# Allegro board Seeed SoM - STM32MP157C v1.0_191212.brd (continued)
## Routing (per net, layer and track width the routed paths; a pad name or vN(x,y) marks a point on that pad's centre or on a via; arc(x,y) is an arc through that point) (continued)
ETH_TX_EN: length 11.8
  TOP w0.089: U3.AB1 8.75,6.82 8.75,6.7 8.02,5.97 8.02,5.95 v1(7.84,5.78)
  LAYER_3 w0.127: v1(0.54,7.56) 0.54,5.76 0.77,5.53 6.43,5.53 6.66,5.76 7.43,5.76 7.45,5.78 v1(7.84,5.78)
  BOTTOM w0.127: J1.28 0.88,7.53 0.86,7.56 v1(0.54,7.56)
ETH_TXD0: length 11.6
  TOP w0.089: U3.AA2 9.13,7.21 8.67,7.21 8.49,7.03 8.49,6.74 7.84,6.09 v1(7.29,6.09)
  LAYER_3 w0.127: v1(0.89,5.93) 0.89,6.2 1.01,6.32 1.45,6.32 1.58,6.19 1.58,5.99 1.71,5.86 2.79,5.86 2.92,5.99 2.92,6.06 3.05,6.19 3.3,6.19 3.43,6.06 3.43,5.99 3.55,5.86 3.81,5.86 3.93,5.99 3.93,6.06 4.06,6.19 4.32,6.19 4.44,6.06 4.44,5.89 4.53,5.8 5.28,5.8 5.8,6.32 6.16,6.32 6.44,6.04 6.76,6.04 6.91,6.19 7.19,6.19 v1(7.29,6.09)
  BOTTOM w0.127: v1(0.89,5.93) J1.20
ETH_TXD1: length 11.8
  TOP w0.089: v1(7.85,6.54) 8.31,7.01 8.31,7.11 8.66,7.45 U3.AA1
  LAYER_3 w0.127: v1(2.01,6.44) 2.2,6.25 2.55,6.25 2.72,6.42 2.72,7 2.82,7.1 3.09,7.1 3.21,6.98 3.21,6.59 3.34,6.47 3.59,6.47 3.72,6.59 3.72,6.98 3.85,7.1 4.08,7.1 4.2,6.98 4.2,6.59 4.33,6.47 4.56,6.47 4.69,6.59 4.69,6.98 4.81,7.1 5.06,7.1 5.16,7 5.16,6.62 5.26,6.52 5.52,6.52 5.64,6.65 5.64,6.98 5.77,7.1 6.15,7.1 6.7,6.54 v1(7.85,6.54)
  BOTTOM w0.127: J1.22 1.9,6.33 v1(2.01,6.44)
ETH_TXD2: length 11.6
  TOP w0.089: v1(7.29,6.87) 7.89,6.87 8.14,7.12 8.14,7.23 8.61,7.7 9.13,7.7 U3.Y2
  LAYER_3 w0.127: v1(7.29,6.87) 6.76,6.87 6.23,7.41 5.06,7.41 4.93,7.53 4.93,7.76 4.8,7.89 4.55,7.89 4.42,7.76 4.42,7.53 4.3,7.41 4.04,7.41 3.91,7.53 3.91,7.76 3.79,7.89 3.53,7.89 3.41,7.76 3.41,7.53 3.28,7.41 1.73,7.41 1.58,7.26 1.58,6.9 1.38,6.7 v1(0.89,6.7)
  BOTTOM w0.127: J1.24 1.43,6.72 0.97,6.72 0.94,6.7 v1(0.89,6.7)
ETH_TXD3: length 11.8
  TOP w0.089: v1(7.83,7.25) 7.9,7.25 8.6,7.95 U3.Y1
  LAYER_3 w0.127: v1(0.87,7.17) 1.22,7.52 1.22,8.07 1.45,8.3 2.28,8.3 2.4,8.17 2.4,7.97 2.53,7.84 2.79,7.84 2.91,7.97 2.91,8.17 3.04,8.3 3.71,8.3 3.84,8.42 3.84,8.83 3.97,8.96 4.22,8.96 4.35,8.83 4.35,8.42 4.48,8.3 5.03,8.3 5.59,7.74 6.43,7.74 6.92,7.25 v1(7.83,7.25)
  BOTTOM w0.127: v1(0.87,7.17) 0.9,7.13 J1.26
FDCAN1_RX: length 21.6
  TOP w0.089: v1(7.17,27.32) 7.55,27.32 9.02,25.85 11.3,25.85 11.37,25.78 12.31,25.78 12.67,25.42 12.67,22.87 13,22.55 13,21.98 12.47,21.45 12.47,18.53 12.63,18.37 12.63,17.2 U3.B8
  LAYER_5 w0.089: v1(7.17,27.32) 7.52,27.68 7.52,28.62 7.14,29 7.14,30.96 v1(7.32,31.13)
  BOTTOM w0.089: J4.68 8.22,31.68 7.68,31.13 v1(7.32,31.13)
FDCAN1_TX: length 21.4
  TOP w0.089: U3.B9 12.88,18.37 12.65,18.61 12.65,19.12 12.65,19.12 12.65,19.24 v1(12.82,19.41)
  LAYER_5 w0.089: v1(12.82,19.41) 12.65,19.59 12.65,21.02 13.82,22.19 13.82,23.23 14.81,24.22 14.81,26.71 13.42,28.11 13.42,29.23 11.13,31.51 8.2,31.51 v1(7.82,31.89)
  BOTTOM w0.089: J4.70 v1(7.82,31.89)
FDCAN2_RX: length 43.7
  TOP w0.089: v1(12.48,8.35) 12.47,8.35 12.38,8.26 U3.Y8
  LAYER_3 w0.089: v1(9.07,31.11) 9.55,30.62 13.71,30.62 13.89,30.45 17.54,30.45 17.89,30.8 v1(18.14,30.8)
  LAYER_5 w0.089: v1(12.48,8.35) 13.57,7.26 18.33,7.26 19.11,8.03 19.11,8.97 19.38,9.25 19.38,16.88 19.26,17.01 19.26,22.29 20.93,23.97 20.93,27.04 18.14,29.84 v1(18.14,30.8)
  BOTTOM w0.089: J4.64 9.02,31.4 9.07,31.35 v1(9.07,31.11)
FDCAN2_TX: length 50.1
  TOP w0.089: U3.AA10 v2(13.39,7.45)
  GND02 w0.089: v1(13.57,5.25) 13.39,5.43 v2(13.39,7.45)
  LAYER_3 w0.089: v1(19.54,30.62) 19.54,30.87 18.69,31.72 13.66,31.72 13.51,31.56 8.97,31.56 v1(8.64,31.89)
  LAYER_5 w0.089: v1(13.57,5.25) 13.57,5.65 14.15,6.24 16.03,6.24 16.9,5.37 19.73,5.37 20.18,5.82 20.18,15.56 21.34,16.71 21.34,17.98 22.55,19.19 22.55,21.3 23.14,21.89 23.14,25.84 19.54,29.45 v1(19.54,30.62)
  BOTTOM w0.089: J4.66 8.62,32.16 8.64,32.14 v1(8.64,31.89)
GPIO_PD4: length 22.4
  TOP w0.089: v1(12.48,34.18) 12.22,33.93 10.55,33.93 10.16,33.54 10.16,30.72 v1(10.59,30.29) ; v1(11.38,19.62) 11.38,19.61 11.31,19.54 11.31,19.32 11.46,19.17 11.46,18.68 11.38,18.6 U3.B6
  LAYER_5 w0.089: v1(11.38,19.62) 11.57,19.81 11.57,21.75 10.75,22.57 10.75,23.7 10.51,23.94 10.51,24.34 10.84,24.67 10.84,25.77 11.07,25.99 11.07,27.31 10.77,27.6 10.32,27.6 10.04,27.88 10.04,28.36 10.59,28.91 v1(10.59,30.29)
  BOTTOM w0.089: v1(12.48,34.18) 12.22,34.43 J4.47
GPIO_PE12: length 18.1
  TOP w0.089: v1(0.48,15.93) 1.29,15.93 2.16,16.81 3.43,16.81 4.45,17.82 4.45,20.72 4.32,20.84 v1(4.07,20.84) ; v1(9.9,19.37) 9.9,19.1 10.13,18.87 10.13,17.21 U3.B4
  LAYER_3 w0.089: v1(9.9,19.37) 5.54,19.37 v1(4.07,20.84)
  BOTTOM w0.089: J1.70 v1(0.48,15.93)
GPIO_PF3: length 42
  TOP w0.089: v1(7.84,9.41) 7.87,9.41 7.88,9.42 7.94,9.42 7.97,9.45 U3.U1
  LAYER_3 w0.089: v1(11.03,35.93) 11.03,36.41 10.67,36.77 6.56,36.77 3.87,34.08 3.08,34.08 2.27,33.26 v1(1.1,33.26)
  LAYER_5 w0.089: v1(7.84,9.41) 7,9.41 3.85,12.56 3.85,12.99 2.77,14.06 2.77,15.05 3.56,15.84 3.56,17.13 4.23,17.81 4.23,20.22 1.1,23.36 v1(1.1,33.26)
  BOTTOM w0.089: J4.53 11.02,35.93 v1(11.03,35.93)
GPIO_PF8: length 51.3
  TOP w0.089: v1(14.2,5.22) 14.2,5.38 13.88,5.7 U3.AC11
  LAYER_3 w0.089: v1(15.79,36.72) 14.93,35.86 11.96,35.86 v1(11.41,36.41)
  LAYER_5 w0.089: v1(14.2,5.22) 14.2,5.77 14.48,6.06 15.96,6.06 16.83,5.19 19.81,5.19 20.46,5.85 20.46,15.57 21.52,16.63 21.52,17.49 23.22,19.19 23.22,21.72 23.37,21.87 23.37,25.87 19.84,29.4 19.84,30.49 19.85,30.49 19.85,33.79 18.83,34.81 16.92,34.81 16.16,35.58 16.16,36.35 v1(15.79,36.72)
  BOTTOM w0.089: J4.51 11.42,36.15 11.41,36.16 v1(11.41,36.41)
GPIO_PF12: length 33.9
  TOP w0.089: U3.Y9 12.88,8.21 12.83,8.27 12.83,8.57 v1(13.13,8.87)
  LAYER_5 w0.089: v1(12.02,36.41) 11.82,36.22 11.82,31.18 13.64,29.35 13.64,28.29 15.09,26.84 15.09,25.26 14.99,25.16 14.99,24.12 14,23.13 14,21.89 13.8,21.68 13.8,18.94 13.24,18.38 13.24,15.1 13.11,14.97 13.11,14.26 12.85,14 12.52,14 11.62,13.1 11.62,10.63 11.61,10.62 11.61,9.62 11.87,9.36 12.65,9.36 v1(13.13,8.87)
  BOTTOM w0.089: v1(12.02,36.41) 12.02,36.11 11.94,36.04 11.94,35.96 11.82,35.84 J4.49
GPIO_PG3: length 33.7
  TOP w0.089: U3.T4 v1(10.65,9.95)
  LAYER_5 w0.089: v1(10.65,9.95) 10.22,10.39 10.22,11.81 8.95,13.08 8.95,15.13 8.01,16.07 8.01,17.06 7.47,17.59 7.47,18.2 7.7,18.43 7.7,20.08 7.32,20.46 7.32,23.76 7.48,23.92 7.48,25.09 6.84,25.73 6.84,32.78 7.35,33.29 7.35,35.5 6.94,35.91 v1(6.94,36.26)
  BOTTOM w0.089: R5.1 3.33,36.21 3.97,36.85 5.54,36.85 6.13,36.26 v1(6.94,36.26)
GPIO_PG11: length 47.2
  TOP w0.089: v1(11.82,8.35) 11.71,8.25 11.71,8.12 U3.Y7
  LAYER_3 w0.089: v1(10.6,36.06) 10.6,35.81 10.79,35.62 15.25,35.62 v1(15.81,36.18)
  LAYER_5 w0.089: v1(15.81,36.18) 15.81,35.51 16.92,34.39 16.92,33.16 18.57,31.51 18.57,29.66 21.9,26.33 21.9,21.76 20.58,20.44 20.58,18.08 19.56,17.06 19.56,9.17 19.28,8.89 19.28,7.95 18.36,7.03 13.14,7.03 v1(11.82,8.35)
  BOTTOM w0.089: J4.55 10.62,35.79 10.6,35.81 v1(10.6,36.06)
GPIO_PI3: length 19.8
  TOP w0.089: U3.E1 8.03,15.45 6.99,16.5 6.99,17.09 5.85,18.23 5.85,21.15 v1(6.15,21.45)
  LAYER_3 w0.089: v1(15.3,20.59) 14.64,20.59 14.49,20.74 14.18,20.74 13.98,20.94 13.98,20.94 13.54,21.38 12.35,21.38 12.22,21.5 11.74,21.5 11.73,21.51 11.48,21.51 11.4,21.59 11.4,21.82 11.31,21.91 11.13,21.91 11.04,21.82 11.04,21.59 10.96,21.51 10.77,21.51 10.69,21.59 10.69,21.82 10.6,21.91 10.42,21.91 10.33,21.82 10.33,21.59 10.25,21.51 10.13,21.51 10.13,21.5 6.45,21.5 6.4,21.45 v1(6.15,21.45)
  BOTTOM w0.089: J2.39 15.43,20.97 15.3,20.84 v1(15.3,20.59)
GPIO_PZ4: length 35.4
  TOP w0.089: U3.G2 9.13,14.21 7.91,14.21 5.03,17.08 5.03,22.2 2.55,24.68 2.55,32.86 6.45,36.77 12.33,36.77 v1(12.5,36.59)
  BOTTOM w0.089: J4.45 12.62,36.22 12.5,36.34 v1(12.5,36.59)
HDMI_CEC: length 25
  TOP w0.089: v1(15.14,8.88) 15.32,8.71 15.32,8.68 15.47,8.52 15.47,8.29 15.38,8.19 U3.Y14
  LAYER_3 w0.127: v1(3.51,3.32) 4.07,3.32 4.78,4.03 6.2,4.03 6.61,3.62 6.61,2.51 7.83,1.29 10.29,1.29 10.81,0.77 15.52,0.77 15.88,1.12 15.88,1.84 15.38,2.35 15.38,7.25 14.8,7.83 14.8,8.53 v1(15.14,8.88)
  BOTTOM w0.127: J1.7 3.73,3.53 v1(3.51,3.32)
HDMI_INT: length 9.1
  TOP w0.089: v1(7.8,7.87) 8.39,8.45 U3.W1
  LAYER_5 w0.127: v1(3.54,3.93) 3.76,4.16 3.76,6.32 5.32,7.87 v1(7.8,7.87)
  BOTTOM w0.127: J1.9 v1(3.54,3.93)
HDMI_NRST: length 22.4
  TOP w0.089: U3.Y17 v2(16.88,7.95)
  GND02 w0.127: v1(17.23,6.26) 17.23,6.53 17.02,6.73 17.02,7.79 16.88,7.93 v2(16.88,7.95)
  LAYER_3 w0.127: v1(4.93,3.52) 4.93,2.96 7.35,0.55 15.68,0.55 16.67,1.54 16.67,3.82 16.18,4.3 16.18,5.22 v1(17.23,6.26)
  BOTTOM w0.127: J1.11 4.75,4.33 4.93,4.16 v1(4.93,3.52)
HES_OUT: length 6
  TOP w0.089: U3.P2 9.13,11.2 8.78,11.2 8.71,11.13 7.91,11.13 7.69,11.36 6.88,11.36 6.23,10.71 R89.2
  TOP w0.127: R90.2 4.82,10.11 4.84,10.12 R89.2
HSE_IN: length 13
  TOP w0.089: R4.2 5.16,2.91 5.36,3.11 5.36,3.95 6.07,4.65 6.07,5.48 5.71,5.83 5.71,6.13 5.9,6.32 6.02,6.43 6.16,6.43 6.41,6.68 6.41,7.59 5.23,8.77 5.23,9.96 5.76,10.49 6.32,10.49 6.98,11.16 7.55,11.16 7.78,10.93 8.68,10.93 8.7,10.95 U3.P1
I2C1_SCL: length 49.5
  TOP w0.089: v1(8.95,4) 9.15,4 10.38,5.23 U3.AC4
  LAYER_3 w0.089: v1(18.38,34.39) 18.13,34.39 18.09,34.43 15.9,34.43 v1(15.73,34.26)
  LAYER_5 w0.089: v1(8.95,4) 9.12,4 11.79,6.67 18.5,6.67 19.79,7.96 19.79,15.66 20.93,16.81 20.93,18.08 22.18,19.32 22.18,21.43 22.64,21.89 22.64,25.85 18.78,29.71 18.78,33.99 v1(18.38,34.39)
  BOTTOM w0.089: v1(15.73,34.26) 15.42,33.95 J4.32
I2C1_SDA: length 49.8
  GND02 w0.089: v2(10.38,7.95) 10.12,7.69 10.12,6.64 10.19,6.57 10.19,3.88 v1(9.9,3.6)
  LAYER_3 w0.089: v1(19.09,30.62) 18.33,31.39 v1(15.96,31.39)
  LAYER_5 w0.089: v1(9.9,3.6) 9.9,4.48 11.92,6.49 16.03,6.49 16.98,5.55 19.66,5.55 20.01,5.9 20.01,15.63 21.14,16.76 21.14,18.03 22.36,19.25 22.36,21.35 22.92,21.91 22.92,25.82 19.11,29.63 19.11,30.36 19.09,30.38 v1(19.09,30.62)
  BOTTOM w0.089: J4.34 15.02,31.92 15.56,31.39 v1(15.96,31.39)
I2C2_SCL: length 47.2
  TOP w0.089: U3.B3 9.63,17.21 9.63,17.74 9.29,18.08 9.29,18.72 9.28,18.74 9.28,19.4 8.39,20.29 8.39,22.72 8.82,23.16 8.82,23.49 8.13,24.17 7.5,24.17 6.74,24.93 6.74,28.41 6.96,28.64 8.08,28.64 8.21,28.51 8.74,28.51 9.61,27.65 v1(9.61,27.1) ; R151.2 27.01,25.72 26.95,25.77 v1(26.95,25.92) 26.95,26.18 27.41,26.64 28.19,26.64 28.87,27.32 U2.4
  LAYER_3 w0.089: v1(9.61,27.1) 9.61,26.76 9.92,26.44 10.79,26.44 11.43,27.09 12.4,27.09 13.16,26.33 13.7,26.33 14.2,25.82 14.68,25.82 15.03,26.17 16.73,26.17 16.83,26.07 19,26.07 19.02,26.05 19.83,26.05 20.19,26.41 20.19,26.53 20.43,26.76 22.82,26.76 24.09,25.49 26.27,25.49 26.7,25.92 v1(26.95,25.92)
  BOTTOM w0.089: v1(9.61,27.1) 9.61,26.51 10.24,25.87 13.29,25.87 13.83,25.33 J2.32
I2C2_SDA: length 48.1
  TOP w0.089: U2.3 28.47,27.32 28.05,26.89 26.78,26.89 v1(25.8,25.91) 26.01,25.7 R152.2 ; v1(8.34,28.82) 8.14,29.02 6.99,29.02 6.56,28.59 6.56,24.86 7.47,23.94 7.88,23.94 8.18,23.64 8.18,21.61 7.68,21.1 7.68,20.64 9.1,19.22 9.1,18.66 9.11,18.65 9.11,18.01 9.38,17.74 U3.A2
  LAYER_3 w0.089: v1(25.8,25.91) 25.05,26.66 25.05,27.27 24.21,28.11 20.66,28.11 19.61,27.07 19.21,27.07 18.96,26.81 18.04,26.81 17.07,27.78 9.38,27.78 v1(8.34,28.82)
  BOTTOM w0.089: J2.34 14.23,25.18 13.36,26.05 10.44,26.05 9.91,26.58 9.91,27.52 8.79,28.63 8.55,28.63 8.54,28.65 8.51,28.65 v1(8.34,28.82)
I2S2_CK: length 11.2
  TOP w0.089: 6.89,6 6.96,6.08 6.96,7.05 7.47,7.56 7.95,7.56 8.6,8.2 9.63,8.2 U3.Y3
  TOP w0.127: 6.89,6 6.89,2.68 6.08,1.87 v1(5.34,1.87)
  BOTTOM w0.127: J1.1 4.9,2.33 5.15,2.08 5.15,2.06 v1(5.34,1.87)
I2S2_SDO: length 10.7
  TOP w0.089: 6.67,6.15 6.79,6.26 6.79,7.38 7.65,8.25 7.9,8.25 8.36,8.7 9.13,8.7 U3.W2
  TOP w0.127: 6.67,6.15 6.67,2.92 6.21,2.47 v1(5.94,2.47)
  BOTTOM w0.127: v1(5.94,2.47) 5.27,3.13 J1.5
I2S2_WS: length 9.5
  TOP w0.089: U3.AC5 10.88,5.2 8.46,2.78 8.18,2.78 v1(8.01,2.61)
  BOTTOM w0.127: v1(8.01,2.61) 7.51,2.11 5.63,2.11 5.01,2.73 J1.3
JTDI: length 27.3
  TOP w0.089: U3.A20 18.38,18.91 19.18,19.71 19.18,20.44 19.36,20.62 19.36,20.97 20.2,21.81 20.83,21.81 21.54,22.52 21.54,24.53 21.92,24.91 21.92,26.89 19.84,28.97 19.84,30.49 19.85,30.49 19.85,31.63 v1(19.46,32.02)
  LAYER_3 w0.089: v1(10.6,32.09) 11.14,32.63 14.66,32.63 14.96,32.33 19.15,32.33 v1(19.46,32.02)
  BOTTOM w0.089: v1(10.6,32.09) 10.62,32.12 J4.56
JTDO_TRACESWO: length 30.8
  TOP w0.089: v1(10.06,34.56) 10.37,34.26 11.81,34.26 12.28,34.73 18.01,34.73 18.04,34.69 18.83,34.69 19.01,34.5 19.01,34.5 19.06,34.45 19.06,33.95 18.76,33.65 18.76,29.8 21.04,27.52 21.04,23.71 20.32,23 20.32,22.44 19,21.12 19,20.76 18.83,20.58 18.83,19.85 18.01,19.04 18.01,17.77 17.88,17.64 U3.A19
  BOTTOM w0.089: J4.58 10.22,34.15 10.06,34.31 v1(10.06,34.56)
JTRST: length 30.3
  TOP w0.076: 19.08,29.2 18.99,29.29
  TOP w0.089: 18.99,29.29 18.57,29.71 18.57,33.75 17.76,34.56 12.35,34.56 11.88,34.09 10.48,34.09 10.39,34 9.86,34 v1(9.68,34.18) ; 19.08,29.2 20.83,27.45 20.83,23.76 20.12,23.05 20.12,22.49 18.83,21.2 18.83,20.87 18.65,20.69 18.65,19.93 17.81,19.09 17.81,17.82 17.63,17.64 17.63,17.2 U3.B19
  BOTTOM w0.089: v1(9.68,34.18) 9.68,33.93 9.82,33.79 J4.60
LES_OUT: length 3.9
  TOP w0.089: 6.6,12.43 7.02,12.43 7.04,12.45 U3.L1
  TOP w0.127: 6.6,12.43 R79.2
LPO_32K: length 24.5
  TOP w0.089: v1(10.7,12.51) 10.65,12.45 U3.L4
  LAYER_3 w0.089: v1(8.64,25.24) 9.15,25.75 12.22,25.75 12.4,25.92 13.33,25.92 13.84,25.42 14.89,25.42 15.43,24.88 17.05,24.88 17.18,25.01 v1(17.43,25.01)
  LAYER_5 w0.089: v1(10.7,12.51) 9.81,13.41 9.81,17.75 9.28,18.28 9.28,19.37 8.56,20.08 8.56,22.55 9,22.98 9,24.5 8.64,24.86 v1(8.64,25.24)
  BOTTOM w0.089: J2.50 v1(17.43,25.01)
LSE_IN: length 4.8
  TOP w0.089: U3.L2 9.13,12.7 6.59,12.7
  TOP w0.127: 6.59,12.7 6.58,12.69 6.1,12.69 5.35,13.44 R2.1
LTDC_B0: length 15.9
  TOP w0.089: U3.K1 7.77,12.95 7.71,13.01 v1(7.46,13.01)
  BOTTOM w0.089: v1(7.46,13.01) 7.95,13.01 8.04,13.1 8.04,13.62 8.13,13.71 8.3,13.71 8.39,13.62 8.39,13.1 8.48,13.01 9.26,13.01 9.4,12.87 9.4,11.9 9.33,11.83 7.98,11.83 7.78,11.62 7.78,10.68 7.9,10.56 8.69,10.56 8.79,10.46 8.79,9.95 8.59,9.74 7.6,9.74 7.29,9.44 5.16,9.44 4.7,8.98 4.7,8.08 4.55,7.93 J1.29
LTDC_B1: length 16.2
  TOP w0.089: v1(11.03,12.92) 10.78,12.92 10.76,12.94 10.58,12.94 10.57,12.95 U3.K4
  LAYER_3 w0.089: v1(3.1,11.67) 2.93,11.85 2.93,12.1 2.7,12.34 2.7,12.49 2.82,12.61 2.98,12.61 3.26,12.34 3.48,12.34 3.75,12.61 4.1,12.61 4.19,12.52 4.19,12.3 4.28,12.21 4.46,12.21 4.55,12.3 4.55,12.52 4.64,12.61 5.13,12.61 5.23,12.7 7.59,12.7 7.8,12.92 v1(11.03,12.92)
  BOTTOM w0.089: J1.27 3.43,7.53 2.87,8.09 2.87,11.45 v1(3.1,11.67)
LTDC_B2: length 17.5
  TOP w0.089: v1(14.4,4.72) 14.4,4.96 14.53,5.1 14.53,5.32 14.15,5.71 14.15,6.68 U3.AB11
  LAYER_3 w0.089: v1(5.56,9.11) 5.78,9.34 7.46,9.34 7.71,9.09 8.55,9.09 8.87,8.78 8.87,7.38 10.39,5.86 12.37,5.86 13.71,4.53 14.21,4.53 v1(14.4,4.72)
  BOTTOM w0.089: v1(5.56,9.11) 5.09,9.11 4.88,8.9 4.88,7.43 4.58,7.13 J1.25
LTDC_B3: length 22.7
  TOP w0.089: v1(10.6,19.21) 10.6,18.96 10.63,18.92 10.63,17.21 U3.B5
  LAYER_3 w0.089: v1(2.86,16.27) 4.29,16.27 5.32,17.29 9.61,17.29 10.6,18.28 v1(10.6,19.21)
  BOTTOM w0.089: J1.23 3.42,6.73 2.7,7.46 2.7,10.79 2.4,11.09 2.4,15.05 2.86,15.51 v1(2.86,16.27)
LTDC_B4: length 20.4
  TOP w0.089: U3.E4 10.57,15.45 v1(10.67,15.35)
  LAYER_3 w0.089: v1(10.67,15.35) 10.36,15.66 5.18,15.66 4.92,15.92 2.62,15.92 v1(2.44,16.09)
  BOTTOM w0.089: J1.21 2.93,6.33 2.5,6.77 2.5,7.33 2.49,7.34 2.49,10.68 2.22,10.96 2.22,15.13 2.62,15.53 2.62,15.92 v1(2.44,16.09)
LTDC_B5: length 16.1
  TOP w0.089: v1(7.35,9.01) 7.88,9.01 8.08,9.21 9.13,9.21 U3.U2
  LAYER_6 w0.089: v1(6.07,9.01) 5.71,8.65 5.71,8.53 5.62,8.44 5.43,8.44 5.34,8.35 5.34,8.17 5.43,8.08 5.62,8.08 5.71,7.99 5.71,7.81 5.62,7.73 5.43,7.73 5.34,7.64 5.34,7.46 5.43,7.37 5.62,7.37 5.71,7.28 5.71,7.1 5.62,7.01 5.43,7.01 5.34,6.93 5.34,6.75 5.43,6.66 5.62,6.66 5.71,6.57 5.71,6.42 5.82,6.32 6.79,6.32 6.91,6.44 6.91,8.88 7.04,9.01 v1(7.35,9.01)
  BOTTOM w0.089: v1(6.07,9.01) 5.82,8.75 5.26,8.75 5.14,8.63 5.14,7 5.05,6.91 4.79,6.91 4.7,6.83 4.7,6.65 4.79,6.56 5.05,6.56 5.14,6.47 5.14,6.14 4.93,5.93 J1.19
LTDC_B6: length 18.6
  TOP w0.089: U3.AB10 13.11,6.68 13.11,6.32 13.2,6.22 13.2,5.59 13.06,5.44 13.06,5.05 13.7,4.41 13.7,2.07 13.77,1.99 v1(13.77,1.74)
  LAYER_3 w0.127: v1(7.4,2.61) 8.34,1.67 10.33,1.67 10.88,1.12 13.14,1.12 v1(13.77,1.74)
  BOTTOM w0.089: v1(7.4,2.61) 6.99,3.01 6.99,5.05 6.5,5.53 J1.17
LTDC_B7: length 22.6
  TOP w0.089: v1(10.93,13.35) 10.75,13.35 10.6,13.2 10.13,13.2 U3.K3
  LAYER_3 w0.089: v1(2.23,15.68) 2.48,15.68 2.49,15.66 3.2,15.66 4.68,14.19 10.09,14.19 v1(10.93,13.35)
  BOTTOM w0.089: J1.15 3.73,5.13 2.32,6.54 2.32,7.26 2.32,7.26 2.32,10.56 2.04,10.83 2.04,15.48 2.05,15.5 2.05,15.5 v1(2.23,15.68)
LTDC_CLK: length 23.9
  TOP w0.089: v1(15.71,3.65) 15.71,3.97 15.45,4.23 15.45,5.81 15.38,5.87 U3.AC14
  LAYER_6 w0.089: v1(15.71,3.65) 15.2,3.14 11.05,3.14 9.25,4.94 9.25,9.97 8.23,10.99 7.27,10.99 6.78,11.48 6.78,13.69 5.59,14.88 v1(4.98,14.88)
  BOTTOM w0.127: J1.63 4.84,14.73 v1(4.98,14.88)
LTDC_DE: length 21.9
  TOP w0.089: v1(14.43,8.35) 14.38,8.3 U3.Y12
  LAYER_3 w0.089: v1(14.43,8.35) 13.97,7.89 11.82,7.89 11.43,8.27 11.43,10.19 9.15,12.47 6.95,12.47 6.58,12.11 4.91,12.11 4.22,11.42 3.36,11.42 2.85,10.91 2.43,10.91 2.34,11 2.34,14.44 2.81,14.91 v1(3.24,14.91)
  BOTTOM w0.089: v1(3.24,14.91) 3.42,15.09 3.44,15.09 3.49,15.13 J1.65
LTDC_G0: length 18.9
  TOP w0.089: v1(11.22,20.13) 11.47,20.13 11.69,19.91 11.69,18.66 11.63,18.6 11.63,16.7 U3.C6
  LAYER_3 w0.089: v1(7.19,20.08) 7.43,20.08 7.58,19.93 10.04,19.93 10.09,19.98 10.82,19.98 10.97,20.13 v1(11.22,20.13)
  BOTTOM w0.089: J1.45 4.7,11.13 4.91,11.34 4.91,11.82 5.72,12.64 5.72,13.99 6.05,14.32 6.05,14.55 6.46,14.95 6.46,16.72 7.22,17.48 7.22,19.8 7.19,19.83 v1(7.19,20.08)
LTDC_G1: length 15.3
  TOP w0.089: U3.C10 13.63,16.21 13.63,15.47 13.86,15.24 v1(13.86,15.12)
  LAYER_3 w0.089: v1(6.46,14.52) 10.73,14.52 11.27,13.98 12.85,13.98 13.14,14.27 13.14,14.94 13.49,15.29 13.69,15.29 v1(13.86,15.12)
  BOTTOM w0.089: v1(6.46,14.52) 6.23,14.28 6.23,14.24 5.92,13.94 5.92,12.59 5.08,11.75 5.08,10.96 4.86,10.73 J1.43
LTDC_G2: length 15.4
  TOP w0.089: v1(7.55,16.98) 7.55,16.51 8.11,15.95 U3.D1
  BOTTOM w0.089: v1(7.55,16.98) 7.33,16.75 6.76,16.75 6.7,16.69 6.7,16.39 6.76,16.32 7.47,16.32 7.55,16.24 7.55,16.04 7.47,15.95 6.75,15.95 6.66,15.87 6.66,15.69 6.75,15.6 7.47,15.6 7.55,15.51 7.55,15.33 7.47,15.24 6.75,15.24 6.66,15.15 6.66,14.98 6.75,14.89 7.47,14.89 7.55,14.8 7.55,14.68 7.47,14.6 7.02,14.6 6.18,13.75 6.18,13.3 6.16,13.29 6.16,12.58 5.26,11.67 5.26,10.66 4.94,10.33 J1.41
LTDC_G3: length 18
  TOP w0.089: U3.C3 v2(9.89,16.45)
  GND02 w0.089: v1(9.97,20.38) 9.97,20.13 9.88,20.04 9.88,20.04 9.35,19.51 9.35,18.66 9.89,18.12 v2(9.89,16.45)
  BOTTOM w0.089: J1.39 4.89,9.93 5.44,10.48 5.44,11.6 6.34,12.5 6.34,13.09 6.35,13.1 6.35,13.68 7.07,14.39 7.65,14.39 7.8,14.54 7.8,16.78 8.13,17.1 8.13,18.52 8.29,18.68 8.29,18.7 v1(9.97,20.38)
LTDC_G4: length 18.4
  TOP w0.089: v1(8.56,18.2) 8.26,17.9 8.26,17.57 U3.B1
  BOTTOM w0.089: J1.37 4.75,9.53 5.62,10.4 5.62,11.49 6.53,12.41 6.53,13.61 7.14,14.21 7.8,14.21 8.01,14.42 8.01,16.73 8.22,16.94 8.7,16.94 8.79,16.85 8.79,16.56 8.88,16.48 9.05,16.48 9.14,16.56 9.14,16.85 9.23,16.94 9.49,16.94 9.58,16.85 9.58,16.49 9.67,16.4 9.85,16.4 9.94,16.49 9.94,16.85 10.03,16.94 10.28,16.94 10.37,17.03 10.37,17.25 10.28,17.34 8.54,17.34 8.31,17.57 8.31,17.95 v1(8.56,18.2)
LTDC_G5: length 16.2
  TOP w0.089: v1(8.36,16.63) 8.36,16.54 8.45,16.45 U3.C1
  BOTTOM w0.089: J1.35 4.6,9.13 5.8,10.33 5.8,11.42 6.71,12.34 6.71,13.49 7.22,14 9.26,14 9.37,14.1 9.37,14.56 9.28,14.65 8.45,14.65 8.36,14.74 8.36,14.91 8.45,15 9.28,15 9.37,15.09 9.37,15.27 9.28,15.36 8.45,15.36 8.36,15.45 8.36,15.62 8.45,15.71 9.28,15.71 9.37,15.8 9.37,16.11 9.28,16.2 8.51,16.2 8.36,16.35 v1(8.36,16.63)
LTDC_G6: length 20.9
  TOP w0.089: U3.E3 9.63,15.2 8.03,15.2 6.76,16.48 6.76,16.87 v1(5.98,17.65)
  BOTTOM w0.089: J1.33 3.75,8.73 3.25,9.24 3.25,10.88 3.61,11.24 3.61,12 2.8,12.82 2.8,14.95 3.56,15.71 3.56,17.01 3.79,17.24 4.35,17.24 4.43,17.33 4.43,17.83 4.52,17.92 4.7,17.92 4.79,17.83 4.79,16.95 4.88,16.86 5.06,16.86 5.15,16.95 5.15,17.83 5.23,17.92 5.41,17.92 5.5,17.83 5.5,17.33 5.59,17.24 5.85,17.24 5.98,17.37 v1(5.98,17.65)
LTDC_G7: length 18.8
  TOP w0.089: v1(6.19,18.33) 7.24,17.28 7.24,16.5 8.04,15.7 9.13,15.7 U3.E2
  BOTTOM w0.089: v1(6.19,18.33) 4.58,18.33 3.38,17.14 3.38,15.79 2.57,14.98 2.57,12.69 3.43,11.83 3.43,11.37 3.05,10.99 3.05,8.55 3.27,8.33 J1.31
LTDC_HSYNC: length 15.5
  TOP w0.089: v1(7.34,9.95) 7.59,9.95 7.64,9.9 8.64,9.9 8.7,9.95 U3.T1
  LAYER_6 w0.089: v1(4.81,15.3) 3.96,15.3 3.87,15.21 3.87,14.44 3.97,14.34 5.54,14.34 5.74,14.14 5.74,13.52 5.83,13.43 6.44,13.43 6.53,13.34 6.53,13.16 6.44,13.07 5.83,13.07 5.74,12.98 5.74,12.8 5.83,12.72 6.44,12.72 6.53,12.63 6.53,12.45 6.44,12.36 5.83,12.36 5.74,12.27 5.74,12.09 5.83,12 6.44,12 6.53,11.92 6.53,11.74 6.44,11.65 5.83,11.65 5.74,11.56 5.74,10.81 6.6,9.95 v1(7.34,9.95)
  BOTTOM w0.089: v1(4.81,15.3) 4.81,15.36 4.63,15.53 J1.67
LTDC_R0: length 17.9
  TOP w0.089: v1(9.06,4.47) 9.36,4.47 10.13,5.24 10.13,6.71 U3.AB4
  LAYER_6 w0.089: v1(3.56,14.6) 3.56,14.35 3.82,14.09 4.7,14.09 5.57,13.22 5.57,10.66 6.61,9.62 7.61,9.62 7.73,9.74 8.06,9.74 9.02,8.78 9.02,4.76 9.06,4.72 v1(9.06,4.47)
  BOTTOM w0.127: v1(3.56,14.6) 3.56,14.54 3.61,14.49 3.61,14.46 3.73,14.33 J1.61
LTDC_R1: length 19.8
  GND02 w0.089: v1(9.33,3.17) 9.33,3.56 9.96,4.19 9.96,5.78 9.86,5.88 v2(9.86,7.46)
  LAYER_6 w0.089: v1(9.33,3.17) 8.59,3.9 8.59,5.35 8.38,5.56 8.38,8.78 8.08,9.08 7.72,9.08 7.44,9.36 6.56,9.36 5.36,10.56 5.36,13.02 4.55,13.83 v1(3.46,13.83)
  BOTTOM w0.127: J1.59 3.56,13.93 v1(3.46,13.83)
LTDC_R2: length 15.5
  TOP w0.089: v1(11.05,15.61) 11.05,15.78 U3.D5
  LAYER_3 w0.089: v1(4.85,16.24) 5.25,15.84 5.74,15.84 5.83,15.93 5.83,16.16 5.92,16.25 6.1,16.25 6.19,16.16 6.19,15.93 6.28,15.84 6.46,15.84 6.54,15.93 6.54,16.16 6.63,16.25 6.81,16.25 6.9,16.16 6.9,15.93 6.99,15.84 7.17,15.84 7.26,15.93 7.26,16.16 7.34,16.25 7.52,16.25 7.61,16.16 7.61,15.93 7.7,15.84 7.92,15.84 8.01,15.93 8.01,16.18 8.1,16.27 8.28,16.27 8.37,16.18 8.37,15.93 8.46,15.84 8.63,15.84 8.72,15.93 8.72,16.18 8.81,16.27 8.99,16.27 9.08,16.18 9.08,15.93 9.17,15.84 9.34,15.84 9.43,15.93 9.43,16.18 9.52,16.27 9.7,16.27 9.79,16.18 9.79,15.93 9.88,15.84 10.06,15.84 10.14,15.93 10.14,16.18 10.23,16.27 10.41,16.27 10.5,16.18 10.5,15.93 10.59,15.84 10.83,15.84 v1(11.05,15.61)
  BOTTOM w0.089: v1(4.85,16.24) 5.34,16.24 5.59,15.99 5.59,15.17 5.29,14.87 5.29,14.7 4.77,14.18 4.77,13.74 4.56,13.53 J1.57
LTDC_R3: length 16.3
  TOP w0.089: v1(10.6,19.65) 10.72,19.65 11.26,19.11 11.26,18.73 11.13,18.6 11.13,16.7 U3.C5
  LAYER_3 w0.089: v1(6.23,19.85) 6.55,19.85 6.72,19.68 10.13,19.68 10.17,19.65 v1(10.6,19.65)
  BOTTOM w0.089: v1(6.23,19.85) 6.29,19.85 6.38,19.76 6.38,18.58 6.55,18.41 6.55,17.57 5.88,16.9 5.88,15.19 5.49,14.8 5.49,14.62 4.98,14.11 4.98,13.56 4.55,13.13 J1.55
LTDC_R4: length 16.6
  TOP w0.089: U3.V3 v2(9.88,8.95)
  GND02 w0.089: v1(5.69,9.77) 5.87,9.59 7.58,9.59 7.71,9.72 8.49,9.72 9.25,8.95 v2(9.88,8.95)
  LAYER_6 w0.089: v1(5.69,9.77) 5,10.46 5,11.96 4.91,12.05 4.74,12.05 4.62,11.93 4.62,8.87 4.53,8.79 4.35,8.79 4.27,8.87 4.27,12.29 4.38,12.4 4.91,12.4 5,12.49 v1(5,12.92)
  BOTTOM w0.089: v1(5,12.92) 4.75,12.92 4.57,12.73 J1.53
LTDC_R5: length 18.7
  TOP w0.089: v1(7.96,3.6) 9,3.6 10.63,5.23 10.63,6.37 10.63,6.38 10.63,6.71 U3.AB5
  LAYER_6 w0.089: v1(3.54,12.83) 4.04,12.33 4.04,7.46 5.84,5.66 7.42,5.66 7.66,5.43 8.08,5.43 8.36,5.15 8.36,4 v1(7.96,3.6)
  BOTTOM w0.089: v1(3.54,12.83) 3.54,12.55 3.75,12.33 J1.51
LTDC_R6: length 15.8
  TOP w0.089: U3.B2 9.13,17.21 9.13,17.71 8.89,17.95 8.89,18.35 8.67,18.58 8.44,18.58 8.35,18.67 8.35,19.51 8.26,19.6 8.09,19.6 8,19.51 8,18.67 7.91,18.58 7.73,18.58 7.64,18.67 7.64,19.51 7.55,19.6 7.37,19.6 7.28,19.51 7.28,18.67 7.2,18.58 6.96,18.58 v1(6.73,18.81)
  BOTTOM w0.089: v1(6.73,18.81) 6.73,17.49 6.06,16.83 6.06,15.12 5.69,14.75 5.69,14.52 5.34,14.17 5.34,12.77 4.51,11.93 J1.49
LTDC_R7: length 17.2
  TOP w0.089: U3.D3 v2(9.88,15.96)
  GND02 w0.089: v2(9.88,15.96) 9.63,16.21 9.63,18.1 8.87,18.86 8.87,19.96 8.89,19.99 v1(8.89,20.24)
  BOTTOM w0.089: J1.47 4.56,11.53 4.68,11.65 4.68,11.85 5.54,12.72 5.54,14.09 5.87,14.42 5.87,14.68 6.25,15.06 6.25,16.73 6.28,16.75 6.28,16.79 7.04,17.55 7.04,18.94 6.63,19.35 6.63,19.96 7.06,20.39 8.5,20.39 8.65,20.24 v1(8.89,20.24)
LTDC_VSYNC: length 16.1
  TOP w0.089: U3.H4 10.51,14.08 10.51,14.11 11.17,14.77 11.21,14.77 11.26,14.82 v1(11.56,14.82)
  LAYER_3 w0.089: v1(5.28,15.3) 5.53,15.3 5.6,15.23 5.6,14.56 5.69,14.47 5.87,14.47 5.96,14.56 5.96,15.24 6.07,15.35 6.25,15.35 6.34,15.26 6.34,14.94 6.43,14.85 6.61,14.85 6.7,14.94 6.7,15.26 6.78,15.35 6.96,15.35 7.05,15.26 7.05,14.86 7.15,14.77 7.33,14.77 7.42,14.86 7.42,15.29 7.51,15.38 7.69,15.38 7.77,15.29 7.77,14.86 7.86,14.77 8.04,14.77 8.13,14.86 8.13,15.29 8.22,15.38 8.4,15.38 8.49,15.29 8.49,14.86 8.57,14.77 8.75,14.77 8.84,14.86 8.84,15.29 8.93,15.38 9.11,15.38 9.2,15.29 9.2,14.86 9.29,14.77 9.46,14.77 9.55,14.86 9.55,15.29 9.64,15.38 9.82,15.38 9.91,15.29 9.91,14.86 10,14.77 11.21,14.77 11.26,14.82 v1(11.56,14.82)
  BOTTOM w0.089: J1.69 4.65,15.93 v1(5.28,15.3)
MMC2_CLK: length 4.1
  TOP w0.089: v1(12.96,18.74) 13.13,18.56 13.13,17.97 13.13,17.97 13.13,16.7 U3.C9
  BOTTOM w0.089: v1(12.96,18.74) 12.02,17.79 R134.1
MMC2_CMD: length 27.3
  TOP w0.089: U3.A10 13.38,18.55 13.32,18.61 13.32,19.12 13.31,19.12 v1(13.31,19.37)
  BOTTOM w0.089: v1(13.31,19.37) 13.31,19.12 13.32,19.12 13.32,17.77 13.64,17.44 15.3,17.44 15.85,18 16.67,18 17.55,18.88 17.56,18.88 17.95,19.27 18.22,19.27 18.31,19.36 18.31,20.6 18.4,20.69 19.08,20.69 19.17,20.6 19.17,20.42 19.08,20.34 18.76,20.34 18.67,20.25 18.67,20.07 18.76,19.98 19.08,19.98 19.17,19.89 19.17,19.71 19.08,19.62 18.76,19.62 18.67,19.54 18.67,19.36 18.76,19.27 19.28,19.27 20.76,20.74 21.22,20.74 21.57,21.1 22.08,21.1 22.69,21.71 22.69,21.94 22.6,22.03 22.32,22.03 22.23,22.12 22.23,22.3 22.32,22.39 22.6,22.39 22.69,22.48 22.69,22.66 22.6,22.74 22.32,22.74 22.23,22.83 22.23,23.01 22.32,23.1 22.6,23.1 22.69,23.19 22.69,24.75 22.6,24.84 22.29,24.84 22.2,24.93 22.2,25.1 22.29,25.19 22.6,25.19 22.69,25.28 22.69,25.46 22.6,25.55 22.29,25.55 22.2,25.64 22.2,25.81 22.29,25.9 22.6,25.9 22.69,25.99 22.69,26.31 22.51,26.49 R133.1
MMC2_DAT0: length 31.4
  TOP w0.089: U3.C13 v2(14.91,16.45)
  GND02 w0.089: v2(14.91,16.45) 14.91,17.18 14.58,17.51 14.58,18.76 14.87,19.05 14.87,20.43 14.6,20.7 14.6,20.75 v1(14.29,21.07)
  LAYER_3 w0.089: v1(3.74,25.73) 3.74,25.42 3.97,25.19 4.73,25.19 4.81,25.26 4.81,25.77 4.88,25.85 6.46,25.85 6.56,25.75 6.56,25.39 6.48,25.31 5.62,25.31 5.52,25.21 5.52,24.41 5.43,24.32 4.64,24.32 4.55,24.23 4.55,23.56 4.68,23.43 5.69,23.43 5.77,23.36 5.77,23.16 5.69,23.08 4.64,23.08 4.55,22.99 4.55,22.77 4.65,22.67 5.59,22.67 5.74,22.52 5.74,22.34 5.62,22.22 5.16,22.22 5.06,22.11 5.06,21.91 5.16,21.81 6.24,21.81 6.31,21.73 9.86,21.73 10.27,22.14 10.51,22.14 10.6,22.23 10.6,23.38 10.7,23.49 11.08,23.49 11.18,23.38 11.18,22.34 11.74,21.78 13.42,21.78 14,21.2 14.15,21.2 14.29,21.07 v1(14.29,21.07)
  BOTTOM w0.089: R125.1 v1(3.74,25.73)
MMC2_DAT1: length 34
  TOP w0.089: U3.B12 14.38,18.84 14.74,19.2 14.74,21.07 13.82,21.99 13.82,23.18 14.1,23.46 14.1,25.6 13.42,26.28 11.57,26.28 11.47,26.38 9.55,26.38 9.07,26.86 9.07,27.63 8.84,27.87 v1(8.35,27.87)
  LAYER_3 w0.089: v1(3.78,29.08) 2.69,29.08 2.6,28.99 2.6,28.04 2.51,27.95 2.34,27.95 2.25,28.04 2.25,28.99 2.16,29.08 2.04,29.08 1.95,28.99 1.95,28.04 1.87,27.95 1.69,27.95 1.6,28.04 1.6,28.99 1.51,29.08 1.27,29.08 1.12,29.23 1.12,29.91 1.27,30.06 1.71,30.06 1.79,29.97 1.79,29.82 1.88,29.73 2.06,29.73 2.15,29.82 2.15,29.97 2.24,30.06 2.42,30.06 2.51,29.97 2.51,29.82 2.59,29.73 2.77,29.73 2.86,29.82 2.86,29.97 2.95,30.06 3.13,30.06 3.22,29.97 3.22,29.82 3.31,29.73 3.48,29.73 3.57,29.82 3.57,29.97 3.66,30.06 3.92,30.06 4.9,29.08 7.13,29.08 v1(8.35,27.87)
  BOTTOM w0.089: R126.1 v1(3.78,29.08)
MMC2_DAT2: length 31.8
  TOP w0.089: v1(8.77,27.5) 8.77,26.89 9.45,26.2 11.42,26.2 11.5,26.11 13.35,26.11 13.92,25.55 13.92,23.58 13.64,23.31 13.64,21.76 13.92,21.48 13.92,17.68 13.88,17.64 U3.A11
  LAYER_3 w0.089: v1(8.77,27.5) 8.77,27.88 7.37,29.28 7.36,29.28 7.27,29.37 7.27,29.59 7.18,29.68 7.01,29.68 6.92,29.59 6.92,29.37 6.83,29.28 6.65,29.28 6.56,29.37 6.56,30.15 6.47,30.24 6.3,30.24 6.21,30.15 6.21,29.37 6.12,29.28 5.59,29.28 5.47,29.4 5.47,30.24 5.29,30.41 5.04,30.41 4.95,30.5 4.95,31.09 4.86,31.18 4.68,31.18 4.6,31.09 4.6,30.15 4.51,30.06 4.33,30.06 4.24,30.15 4.24,31.09 4.15,31.18 2.67,31.18 2.52,31.03 2.52,30.52 2.63,30.41 v1(3.33,30.41)
  BOTTOM w0.089: R127.1 3.72,32.17 3.33,31.79 v1(3.33,30.41)
MMC2_DAT3: length 28.3
  TOP w0.089: U3.B13 14.61,17.23 14.61,18.76 14.92,19.07 14.92,21.24 14.02,22.14 14.02,23.1 14.28,23.36 14.28,25.65 13.49,26.44 11.64,26.44 11.53,26.56 9.63,26.56 9.25,26.94 9.25,27.69 8.68,28.26 v1(7.15,28.26)
  LAYER_3 w0.089: v1(7.15,28.26) 6.9,28.26 6.82,28.18 4.11,28.18 3.33,27.4 3.33,25.49 4.35,24.48 v1(4.35,22.19)
  BOTTOM w0.089: R128.1 4.36,22.2 v1(4.35,22.19)
MMC2_DAT4: length 29.5
  TOP w0.089: U3.A13 14.79,17.55 14.79,18.49 v1(15.37,19.07)
  LAYER_3 w0.089: v1(3.76,24.12) 3.76,23.76 3.7,23.69 3.5,23.69 3.41,23.6 3.41,23.43 3.5,23.34 3.7,23.34 3.79,23.25 3.79,23.07 3.7,22.98 3.5,22.98 3.41,22.89 3.41,22.71 3.5,22.63 3.7,22.63 3.79,22.54 3.79,22.36 3.7,22.27 3.5,22.27 3.41,22.18 3.41,22 3.5,21.91 3.7,21.91 3.79,21.83 3.79,21.5 4.07,21.23 4.47,21.23 5.29,20.41 5.54,20.41 5.63,20.5 5.63,20.65 5.72,20.74 5.89,20.74 5.98,20.65 5.98,20.5 6.07,20.41 6.25,20.41 6.34,20.5 6.34,20.65 6.43,20.74 6.61,20.74 6.69,20.65 6.69,20.5 6.78,20.41 6.96,20.41 7.05,20.5 7.05,20.65 7.14,20.74 7.32,20.74 7.41,20.65 7.41,20.5 7.5,20.41 8.49,20.41 8.77,20.69 11.54,20.69 11.82,20.41 11.82,19.31 11.73,19.22 11.45,19.22 11.36,19.13 11.36,18.95 11.45,18.86 11.73,18.86 11.82,18.77 11.82,18.6 11.73,18.51 11.45,18.51 11.36,18.42 11.36,18.24 11.45,18.15 11.73,18.15 11.82,18.06 11.82,17.8 12.2,17.42 12.51,17.42 12.6,17.5 12.6,17.96 12.68,18.05 12.86,18.05 12.95,17.96 12.95,17.5 13.04,17.42 13.22,17.42 13.31,17.5 13.31,17.96 13.4,18.05 13.57,18.05 13.66,17.96 13.66,17.5 13.75,17.42 13.93,17.42 14.02,17.5 14.02,17.96 14.11,18.05 14.28,18.05 14.37,17.96 14.37,17.5 14.46,17.42 15.3,17.42 15.54,17.66 15.54,18.89 v1(15.37,19.07)
  BOTTOM w0.089: v1(3.76,24.12) 4.02,24.12 4.03,24.14 R129.1
MMC2_DAT5: length 32
  TOP w0.089: U3.A8 12.38,18.37 12.27,18.48 12.27,22.56 12.5,22.79 12.5,25.3 12.17,25.62 10.5,25.62 10.47,25.65 8.36,25.65 8.23,25.52 8.23,24.58 8.16,24.5 7.97,24.5 7.88,24.59 7.88,24.86 7.79,24.95 7.57,24.95 7.48,25.04 7.48,25.21 7.57,25.3 7.79,25.3 7.88,25.39 7.88,25.57 7.79,25.66 7.57,25.66 7.48,25.75 7.48,25.92 7.57,26.01 7.79,26.01 7.88,26.1 7.88,26.66 7.68,26.86 v1(7.15,26.86)
  LAYER_3 w0.089: v1(3.75,27.36) 4,27.36 4.14,27.22 4.14,25.51 4.23,25.42 4.45,25.42 4.54,25.51 4.54,26.31 4.61,26.39 4.61,27.83 4.7,27.92 4.88,27.92 4.97,27.83 4.97,26.62 5.06,26.53 5.24,26.53 5.33,26.62 5.33,27.83 5.41,27.92 5.59,27.92 5.68,27.83 5.68,26.95 5.77,26.86 5.93,26.86 6.02,26.95 6.02,27.84 6.11,27.93 6.29,27.93 6.38,27.84 6.38,26.56 6.47,26.47 6.75,26.47 v1(7.15,26.86)
  BOTTOM w0.089: v1(3.75,27.36) 4,27.36 4.01,27.36 R130.1
MMC2_DAT6: length 31.9
  TOP w0.089: U3.C11 v2(13.85,16.45) ; v1(7.15,27.8) 7.4,27.8 9.17,26.03 11.36,26.03 11.44,25.95 13.27,25.95 13.74,25.47 13.74,24.52 13.65,24.43 13,24.43 12.91,24.34 12.91,24.17 13,24.08 13.65,24.08 13.74,23.99 13.74,23.66 13.47,23.38 13.47,21.68 13.74,21.41 13.74,20.86 13.53,20.65 13.46,20.65 v1(13.29,20.48)
  GND02 w0.089: v2(13.85,16.45) 13.18,16.45 12.22,17.42 12.22,20.39 12.31,20.48 v1(13.29,20.48)
  LAYER_3 w0.089: v1(3.28,28.69) 3.03,28.69 3.01,28.67 3,28.67 2.85,28.51 2.85,27.75 2.95,27.65 3.28,27.65 4.53,28.9 5.6,28.9 5.69,28.81 5.69,28.55 5.78,28.46 5.95,28.46 6.04,28.55 6.04,28.81 6.13,28.9 6.31,28.9 6.4,28.81 6.4,28.55 6.49,28.46 6.67,28.46 6.75,28.55 6.75,28.81 6.84,28.9 7.01,28.9 7.46,28.45 7.46,27.87 7.4,27.8 v1(7.15,27.8)
  BOTTOM w0.089: v1(3.28,28.69) 3.28,29.63 4.29,30.64 R131.1
MMC2_DAT7: length 30.8
  TOP w0.089: v1(14.33,19.28) 14.16,19.1 14.16,17.23 U3.B11
  LAYER_3 w0.089: v1(3,25.34) 3.18,25.16 3.41,25.16 4.1,24.47 4.1,23.99 3.99,23.88 3.99,21.63 4.2,21.43 4.98,21.43 5.41,21 6.91,21 7.24,21.33 10.2,21.33 10.21,21.33 11.66,21.33 11.99,21 11.99,20.5 12.08,20.41 12.18,20.41 12.27,20.32 12.27,20.15 12.18,20.06 12.08,20.06 11.99,19.97 11.99,19.79 12.08,19.7 12.18,19.7 12.27,19.61 12.27,19.44 12.18,19.35 12.08,19.35 11.99,19.26 11.99,18.81 12.45,18.35 14.18,18.35 14.33,18.51 v1(14.33,19.28)
  BOTTOM w0.089: R132.1 4.27,33.82 4.11,33.67 4.11,33.49 2.93,32.31 2.93,25.66 3,25.59 v1(3,25.34)
MOC1: length 13.8
  TOP w0.089: U3.N2 9.06,11.78 7.93,11.78 7.7,11.55 7.46,11.55 7.34,11.67 v1(7.19,11.67)
  LAYER_3 w0.089: v1(7.19,11.67) 4.85,11.67 4.4,11.22 3.41,11.22 2.93,10.73 2.25,10.73 2.11,10.87 2.11,14.24 v1(0.84,15.51)
  BOTTOM w0.089: J1.68 1.42,15.51 v1(0.84,15.51)
MOC2: length 43
  TOP w0.089: 8.6,10.29 9.05,10.29 U3.T2
  TOP w0.127: v1(8.39,10.22) 8.53,10.22 8.6,10.29
  LAYER_3 w0.089: v1(1.85,33.69) 2.1,33.69 2.13,33.72 2.14,33.72 2.8,34.38 3.87,34.38 6.48,37 12.65,37 13.01,36.64 v1(13.01,36.39)
  LAYER_5 w0.089: v1(1.85,33.69) 2.2,33.35 2.2,31.59 1.68,31.08 1.68,24.17 4.63,21.23 4.63,16.78 4.27,16.42 4.27,12.71 6.06,10.92 6.44,10.92 6.48,10.96 7.64,10.96 v1(8.39,10.22)
  BOTTOM w0.089: J4.43 13.02,36 13.01,36.01 v1(13.01,36.39)
NRST: length 48.9
  TOP w0.089: v1(11.16,12.45) 10.98,12.28 10.96,12.28 10.89,12.2 10.13,12.2 U3.M3 ; v1(24.41,27.42) 24.24,27.25 24.24,24.87 24.42,24.68 R153.1
  LAYER_3 w0.089: v1(8.34,27.37) 8.53,27.19 8.9,27.19 9.31,27.6 13.05,27.6 v1(13.99,26.66) 14.83,27.5 16.99,27.5 17.88,26.61 19,26.61 19.28,26.89 19.82,26.89 20.6,27.68 24.16,27.68 v1(24.41,27.42)
  LAYER_5 w0.089: v1(8.34,27.37) 8.34,27.13 8.31,27.1 8.31,24.88 8.82,24.37 8.82,23.05 8.39,22.62 8.39,19.9 9.07,19.22 9.07,18.1 9.55,17.62 9.55,13.22 10.58,12.2 10.91,12.2 v1(11.16,12.45) ; v1(10.57,31.13) 10.89,30.81 10.89,29.76 v1(13.99,26.66)
  BOTTOM w0.089: v1(10.57,31.13) 10.82,31.13 10.83,31.12 11.05,31.12 11.82,31.9 J4.50 ; v1(13.99,26.66) 14,26.67 14,26.7 14.37,27.07 R135.1
OTG_FS_DM: length 65.4
  TOP w0.089: U3.AA18 v2(17.38,7.46)
  GND02 w0.089: v2(17.38,7.46) 17.38,6.69 17.87,6.21 17.87,5.47 18.88,4.46 18.88,3.32 18.88,3.32 18.88,3.09 19.41,2.56 19.77,2.56 v1(19.99,2.33)
  LAYER_6 w0.135: v1(19.99,2.33) 20.11,2.45 20.68,2.45 21.01,2.77 21.01,6.02 19.65,7.38 19.65,17.26 22.84,20.46 25.12,20.46 26.6,21.94 26.6,29.02 25.35,30.28 14.58,30.28 13.64,29.34 11.87,29.34 11.46,29.74 8.14,29.74 8,29.88 8,30.34 v1(8.18,30.52)
  BOTTOM w0.114: J2.4 8.23,24.86 8.17,24.92 8.17,26.46 7.98,26.65 7.98,30.32 v1(8.18,30.52)
OTG_FS_DP: length 65.3
  TOP w0.089: U3.AB19 17.88,6.96 v2(17.86,6.96)
  GND02 w0.089: v2(17.86,6.96) 17.79,6.96 17.68,6.85 17.68,6.67 18.14,6.21 18.14,5.48 18.41,5.21 18.53,5.21 18.75,5.43 18.85,5.43 19,5.27 19,5.15 18.81,4.96 18.81,4.8 19.13,4.49 19.13,3.14 19.51,2.77 19.88,2.77 v1(20.02,2.91)
  LAYER_6 w0.135: v1(7.5,30.52) 7.68,30.34 7.68,29.75 8.01,29.43 8.7,29.43 8.83,29.29 8.83,29.16 8.97,29.02 9.24,29.02 9.37,29.16 9.37,29.29 9.51,29.43 11.33,29.43 11.74,29.02 13.77,29.02 14.71,29.96 25.22,29.96 26.29,28.89 26.29,22.07 24.99,20.77 22.71,20.77 19.33,17.39 19.33,7.26 20.7,5.89 20.7,2.9 20.55,2.76 20.17,2.76 v1(20.02,2.91)
  BOTTOM w0.114: v1(7.5,30.52) 7.7,30.32 7.7,26.53 7.89,26.34 7.89,24.92 7.83,24.86 J2.2
OTG_VBUS: length 46.3
  TOP w0.089: v1(18.57,3.83) 18.9,4.16 18.9,4.82 17.88,5.84 U3.AC19
  LAYER_5 w0.076: 22.92,16.3 22.92,11.86 22.6,11.54
  LAYER_5 w0.089: v1(18.57,3.83) 19.2,3.19 19.71,3.19 21.24,4.72 21.24,9.19 21.51,9.46 21.51,10.45 22.6,11.54 ; 22.92,16.3 22.92,17.22 23.93,18.23 23.93,21.4 24.36,21.83 24.36,25.77 v1(23.8,26.33)
  LAYER_6 w0.089: v1(23.8,26.33) 23.19,25.72 19.27,25.72 17.87,24.32 9.66,24.32 v1(9.05,24.93)
  BOTTOM w0.203: J2.8 9.03,24.92 v1(9.05,24.93)
PA0_WKUP: length 72.3
  TOP w0.089: U3.AB3 9.63,6.7 9.63,5.93 8.36,4.66 v1(7.32,4.66) ; v1(25.69,28.18) 25.86,28.35 25.92,28.35 26.41,28.84 U2.43
  LAYER_3 w0.089: v1(0.72,32.71) 2.19,32.71 3.23,33.75 5.37,33.75 5.75,34.13 6.01,34.13 6.39,33.75 12.63,33.75 v1(12.96,34.08) 14.25,35.37 22.71,35.37 24.67,33.42 24.67,30.75 25.69,29.73 v1(25.69,28.18)
  LAYER_5 w0.089: v1(0.72,32.71) 0.92,32.5 0.92,23.29 4.06,20.15 4.06,17.91 3.38,17.24 3.38,15.91 2.54,15.08 2.54,13.33 5.79,10.08 5.82,10.08 6.01,9.9 6.01,9.86 7.17,8.7 7.39,8.7 7.72,8.37 7.76,8.37 8.36,7.76 8.36,4.94 8.08,4.66 v1(7.32,4.66)
  BOTTOM w0.089: J4.44 13.02,33.77 12.96,33.83 v1(12.96,34.08)
PMIC_WAKEUP: length 57
  TOP w0.089: v1(7.09,13.33) 7.68,13.33 7.78,13.22 9.11,13.22 U3.K2 ; v1(25.76,26.61) 26.24,27.09 27.85,27.09 28.07,27.32 U2.2
  LAYER_3 w0.089: v1(4.81,33.37) 4.82,33.37 4.96,33.5 12.89,33.5 v1(13.47,34.08) 14.2,34.81 21.34,34.81 21.67,35.14 22.56,35.14 24.29,33.42 24.29,30.75 24.77,30.27 24.77,28.43 25.12,28.08 25.76,27.44 v1(25.76,26.61)
  LAYER_5 w0.089: v1(7.09,13.33) 6.58,13.33 5.95,13.96 5.95,15.87 5.19,16.63 5.19,22.16 4.3,23.05 4.3,32.86 v1(4.81,33.37)
  BOTTOM w0.089: v1(13.47,34.08) 13.47,33.83 13.42,33.79 J4.42
PONKEYN: length 24.4
  TOP w0.089: U2.17 33.64,30.04 33.69,29.99 v1(33.94,29.99)
  LAYER_3 w0.089: v1(21.62,31.13) 19.84,31.13 18.83,32.15 14.76,32.15 14.48,32.43 13.54,32.43 13.22,32.1 v1(12.62,32.1)
  LAYER_5 w0.089: v1(21.62,31.13) 21.62,30.88 22.13,30.37 26.95,30.37 27.46,29.86 32.92,29.86 33.05,29.99 v1(33.94,29.99)
  BOTTOM w0.089: J4.46 v1(12.62,32.1)
PWR_ON: length 60.1
  TOP w0.089: U2.44 26.45,28.44 25.77,27.77 v1(24.99,27.77) ; v1(7.29,10.63) 7.54,10.63 7.64,10.53 9.12,10.53 9.2,10.45 U3.R2
  TOP w0.127: v1(3.56,10.63) 3.3,10.63 R88.1
  LAYER_3 w0.089: v1(1.48,32.2) 5.8,32.2 5.9,32.3 8.72,32.3 9.23,31.79 13.26,31.79 13.57,32.11 v1(13.82,32.11) 14,31.93 18.79,31.93 22.38,28.34 24.42,28.34 v1(24.99,27.77)
  LAYER_3 w0.127: v1(3.56,10.63) v1(7.29,10.63)
  LAYER_5 w0.089: v1(7.29,10.63) 6.1,10.63 4.05,12.68 4.05,14.56 3.76,14.85 3.76,17.06 4.45,17.75 4.45,21.16 1.5,24.1 1.5,31.92 1.48,31.95 v1(1.48,32.2)
  BOTTOM w0.089: J4.40 v1(13.82,32.11)
QSPI_BK1_IO0: length 50.2
  TOP w0.089: v1(14.02,3.78) 14.02,4.34 13.24,5.12 13.24,5.37 13.38,5.51 U3.AC10
  LAYER_5 w0.089: v1(23.88,24.4) 23.88,24.27 23.73,24.12 23.73,21.71 23.58,21.56 23.58,19.05 21.9,17.37 21.9,16.43 21.75,16.27 21.75,11.4 20.86,10.51 20.86,5.07 19.99,4.21 19.38,4.21 18.76,4.84 16.68,4.84 15.86,5.66 15.19,5.66 14.89,5.35 14.89,4.39 14.28,3.78 v1(14.02,3.78)
  LAYER_6 w0.089: v1(9.81,23.74) 9.98,23.92 10.37,23.92 11.1,23.18 11.1,22.84 11.3,22.64 14.51,22.64 14.9,22.26 15.3,22.26 15.49,22.44 15.49,23.4 15.7,23.61 18.24,23.61 19.02,24.4 21.49,24.4 21.86,24.03 23.51,24.03 v1(23.88,24.4)
  BOTTOM w0.089: v1(9.81,23.74) 9.81,23.82 9.83,23.84 J2.12
QSPI_BK1_IO1: length 45.3
  TOP w0.089: U3.Y18 v2(17.39,7.95)
  GND02 w0.089: v1(19.49,3.64) 19.49,3.89 19.41,3.97 19.41,5.27 18.83,5.86 18.83,6.52 v2(17.39,7.95)
  LAYER_5 w0.089: v1(24.04,23.92) 24.04,23.67 24.03,23.66 24.03,21.76 23.75,21.48 23.75,18.3 22.51,17.06 22.43,17.06 22.17,16.8 22.17,16 22.56,15.61 22.56,14.37 22.46,14.27 22.46,14.27 22.21,14.03 22.21,11.61 21.06,10.46 21.06,4.95 19.76,3.64 v1(19.49,3.64)
  LAYER_6 w0.089: v1(24.04,23.92) 23.79,23.92 23.73,23.85 21.35,23.85 21.04,24.17 19.05,24.17 18.31,23.43 15.96,23.43 15.7,23.18 15.7,22.41 15.15,21.86 11.36,21.86 10.81,22.41 10.81,23.18 10.52,23.47 v1(10.23,23.47)
  BOTTOM w0.089: v1(10.23,23.47) 10.23,23.82 10.23,23.82 J2.14
QSPI_BK1_IO2: length 55.9
  TOP w0.089: v1(14.74,1.88) 14.53,2.09 14.53,3.67 14.71,3.85 14.71,5.43 14.38,5.76 U3.AB12
  LAYER_5 w0.089: v1(14.74,1.88) 14.74,1.18 15.3,0.63 19.74,0.63 21.77,2.66 21.77,8.55 22.56,9.34 22.56,10.58 24.65,12.67 24.65,15.55 24.62,15.57 24.62,18.06 25.05,18.48 25.05,24.63 25.18,24.76 25.18,26.42 24.81,26.79 v1(24.57,26.79)
  LAYER_6 w0.089: v1(10.52,24.92) 10.94,24.5 17.8,24.5 19.19,25.9 22.81,25.9 23.7,26.79 v1(24.57,26.79)
  BOTTOM w0.089: J2.16 10.63,24.79 10.52,24.91 v1(10.52,24.92)
QSPI_BK1_IO3: length 54.2
  TOP w0.089: v1(15.27,1.16) 15.45,1.33 15.45,1.39 15.66,1.6 15.66,2.19 15.4,2.45 15.4,3.79 15.37,3.82 15.37,3.82 15.31,3.88 15.31,3.88 15.24,3.95 15.24,5.73 15.13,5.84 15.13,7.2 U3.AA13
  LAYER_5 w0.089: v1(15.27,1.16) 15.6,0.83 19.61,0.83 21.59,2.81 21.59,8.65 22.38,9.44 22.38,10.73 23.83,12.18 23.83,15.64 24.16,15.97 24.16,17.92 24.85,18.61 24.85,25.19 24.87,25.21 v1(24.87,26.23)
  LAYER_6 w0.089: v1(24.87,26.23) 24.29,26.23 23.6,25.54 19.34,25.54 17.94,24.15 11.32,24.15 v1(11.03,23.86)
  BOTTOM w0.089: J2.18 11.03,23.89 11.03,23.89 v1(11.03,23.86)
QSPI_BK2_IO0: length 54.4
  TOP w0.089: U3.AA11 13.63,7.2 13.63,5.7 13.88,5.45 13.88,4.79 14.33,4.33 v1(14.33,1.18)
  LAYER_5 w0.089: v1(25.56,23.94) 25.56,23.69 25.61,23.65 25.61,23.64 25.71,23.54 25.71,18.69 25.46,18.43 25.46,18.11 25.46,18.1 25.46,13.11 22.76,10.4 22.76,9.26 21.95,8.45 21.95,2.51 19.88,0.45 15.07,0.45 v1(14.33,1.18)
  LAYER_6 w0.089: v1(11.54,23.45) 11.78,23.45 11.9,23.33 14.13,23.33 14.58,23.79 18.16,23.79 19,24.63 22.15,24.63 22.24,24.71 24.54,24.71 25.31,23.94 v1(25.56,23.94)
  BOTTOM w0.089: v1(11.54,23.45) 11.54,23.7 11.43,23.8 J2.20
QSPI_BK2_IO1: length 52.6
  TOP w0.089: v1(15.27,1.79) 15.27,2.25 15.2,2.32 15.2,3.72 15.19,3.72 15.19,3.75 15.07,3.88 15.07,5.65 14.88,5.84 U3.AC13
  LAYER_5 w0.089: v1(15.27,1.79) 16.06,1.01 19.49,1.01 21.42,2.94 21.42,8.91 21.69,9.18 21.69,10.37 23.09,11.78 23.09,15.54 23.96,16.4 23.96,18 24.67,18.71 24.67,25.99 23.86,26.8 23.86,27.07 23.87,27.09 v1(23.87,27.33)
  LAYER_6 w0.089: v1(23.87,27.33) 23.68,27.15 23.68,27.12 22.64,26.08 19.12,26.08 17.75,24.7 11.92,24.7 11.76,24.86 v1(11.76,25.19)
  BOTTOM w0.089: J2.22 11.83,24.87 11.76,24.94 v1(11.76,25.19)
QSPI_BK2_IO2: length 47.2
  TOP w0.089: U3.AA9 12.63,7.21 12.63,6.17 12.58,6.11 12.58,5.86 12.83,5.61 12.83,4.99 13.38,4.44 v1(13.38,3.9)
  LAYER_5 w0.089: v1(23.87,25.28) 23.69,25.1 23.69,25.02 23.55,24.88 23.55,21.78 23.4,21.63 23.4,19.12 21.72,17.44 21.72,16.5 21.57,16.35 21.57,11.47 20.64,10.54 20.64,5.77 19.88,5.01 16.76,5.01 15.91,5.86 15.14,5.86 14.71,5.43 14.71,4.46 14.51,4.26 13.64,4.26 13.56,4.17 13.56,4.08 v1(13.38,3.9)
  LAYER_6 w0.089: v1(12.18,23.74) 12.41,23.97 18.09,23.97 19.44,25.31 21.68,25.31 21.72,25.28 v1(23.87,25.28)
  BOTTOM w0.089: J2.24 12.23,23.79 v1(12.18,23.74)
QSPI_BK2_IO3: length 26.3
  TOP w0.089: v1(16.9,8.88) 16.72,8.71 16.63,8.71 U3.Y15
  LAYER_5 w0.089: v1(16.26,25.87) 16.26,25.19 16.54,24.91 16.54,17.54 17.94,16.15 18.29,16.15 18.67,15.76 18.67,9.54 18.12,8.99 17.58,8.99 17.34,9.24 17,9.24 16.9,9.13 v1(16.9,8.88)
  LAYER_6 w0.089: v1(16.26,25.87) 15.93,26.2 15.01,26.2 14.38,25.57 v1(12.98,25.57)
  BOTTOM w0.089: v1(12.98,25.57) 12.63,25.21 J2.26
QSPI_CLK: length 24.1
  TOP w0.089: v1(16.88,8.38) 16.71,8.2 16.7,8.2 16.59,8.08 16.51,8.08 U3.Y16
  LAYER_5 w0.089: v1(16.88,8.38) 16.57,8.69 16.57,9.39 17.22,10.04 17.22,10.05 17.4,10.23 17.89,10.23 17.89,10.23 18.05,10.23 18.47,10.66 18.47,15.54 18.11,15.89 17.2,15.89 16.29,16.8 16.29,22.16 15.73,22.72 15.73,23.92 15.78,23.97 v1(15.78,25.21)
  LAYER_6 w0.089: v1(15.78,25.21) 15.53,24.96 13.29,24.96 13.22,25.03 v1(12.98,25.03)
  BOTTOM w0.089: v1(12.98,25.03) 12.98,24.83 13.03,24.79 J2.28
SAI2_FSAM: length 15.2
  TOP w0.089: U3.F2 8,14.95 5.59,17.36 5.59,21.36 6.15,21.92 v1(6.15,22.16)
  LAYER_3 w0.089: v1(10.24,22.47) 10.07,22.29 10.07,22.27 9.73,21.94 6.38,21.94 v1(6.15,22.16)
  BOTTOM w0.089: J2.15 10.63,22.08 v1(10.24,22.47)
SAI2_MCLKA: length 11.9
  TOP w0.089: v1(12.02,14.7) 12.02,14.95 11.38,15.58 U3.D6
  LAYER_5 w0.089: v1(11.54,23) 12.14,22.4 12.14,21.75 11.93,21.54 11.93,19.36 11.56,18.99 11.56,15.41 12.02,14.95 v1(12.02,14.7)
  BOTTOM w0.089: J2.19 11.43,22.76 11.54,22.86 v1(11.54,23)
SAI2_SCKAM: length 8.6
  TOP w0.089: U3.F3 v2(9.88,14.97)
  GND02 w0.089: v1(8.89,21) 8.56,20.67 8.56,18.91 9.43,18.05 9.43,15.43 v2(9.88,14.97)
  BOTTOM w0.089: J2.13 10.23,21.26 9.97,21 v1(8.89,21)
SAI2_SDAM: length 11.5
  TOP w0.089: U3.F4 v2(10.37,14.95)
  GND02 w0.089: v1(8.06,20.77) 7.88,20.59 7.88,19.35 8.29,18.94 8.29,18.93 9.25,17.97 9.25,15.23 9.77,14.71 10.13,14.71 v2(10.37,14.95)
  BOTTOM w0.089: J2.17 11.03,20.9 10.82,20.69 8.38,20.69 8.3,20.77 v1(8.06,20.77)
SAI2_SDBM: length 22.1
  TOP w0.089: U3.Y10 13.38,8.15 v1(13.14,8.4)
  LAYER_3 w0.089: v1(11.82,22.21) 12.02,22.01 13.45,22.01 13.85,21.61 14.76,21.61 16.21,20.16 16.21,17.44 14.74,15.97 14.74,14.16 14.43,13.85 12.98,13.85 12.91,13.78 12.28,13.78 11.66,13.16 11.66,9.59 12.02,9.24 12.58,9.24 12.81,9.01 12.81,8.73 v1(13.14,8.4)
  BOTTOM w0.089: J2.21 11.83,22.15 11.82,22.16 v1(11.82,22.21)
SDMMC1_CK: length 17.7
  TOP w0.089: U3.D13 14.88,15.95 v2(14.86,15.97)
  GND02 w0.089: v1(14.41,20.39) 14.69,20.1 14.69,19.12 14.41,18.84 14.41,17.43 14.65,17.19 14.65,16.35 14.66,16.34 14.66,16.17 v2(14.86,15.97)
  LAYER_5 w0.089: v1(15.17,22.57) 15.17,21.68 16.01,20.85 16.01,20.49 15.92,20.4 15.79,20.4 15.7,20.31 15.7,20.13 15.79,20.05 15.92,20.05 16.01,19.96 16.01,19.78 15.92,19.69 15.79,19.69 15.7,19.6 15.7,19.42 15.79,19.33 15.92,19.33 16.01,19.25 16.01,19.07 15.92,18.98 15.79,18.98 15.7,18.89 15.7,18.71 15.79,18.62 15.92,18.62 16.01,18.53 16.01,18.36 15.92,18.27 15.79,18.27 15.7,18.18 15.7,18 15.79,17.91 15.92,17.91 16.01,17.82 16.01,17.62 15.85,17.47 14.81,17.47 14.69,17.59 14.69,18.05 14.77,18.14 14.87,18.14 14.96,18.23 14.96,18.41 14.87,18.5 14.77,18.5 14.69,18.59 14.69,18.76 14.77,18.85 14.87,18.85 14.96,18.94 14.96,19.12 14.87,19.21 14.77,19.21 14.69,19.3 14.69,20.11 v1(14.41,20.39)
  BOTTOM w0.089: v1(15.17,22.57) 15.17,22.3 15.03,22.16 J2.37
SDMMC1_CMD: length 17.9
  GND02 w0.089: v2(14.38,15.95) 14.11,16.23 14.11,16.56 13.64,17.03 13.64,17.21 13.5,17.35 12.61,17.35 12.52,17.44 12.52,17.62 12.61,17.7 13.53,17.7 13.62,17.79 13.62,17.97 13.53,18.06 12.56,18.06 12.47,18.15 12.47,18.33 12.57,18.42 13.46,18.42 13.52,18.49 13.52,18.93 13.41,19.05 12.55,19.05 12.48,19.12 12.48,19.98 12.65,20.16 v1(12.96,20.16)
  BOTTOM w0.089: v1(12.96,20.16) 13.21,20.16 13.21,20.16 13.54,20.16 13.67,20.03 13.67,17.91 13.76,17.82 13.93,17.82 14.02,17.91 14.02,19.97 14.12,20.08 14.88,20.08 14.98,20.18 14.98,20.57 14.63,20.93 J2.35
SDMMC1_D0: length 17.9
  TOP w0.089: U3.D18 v2(17.38,15.92)
  GND02 w0.089: v2(17.38,15.92) 17.57,16.1 17.58,16.1 18.19,16.72 18.19,19.52 18.95,20.28 18.95,21.37 19.99,22.42 19.99,23.42 19.97,23.44 v1(19.97,23.69)
  LAYER_3 w0.089: v1(12.98,23) 13.52,23 14.38,23.87 18.99,23.87 19.45,23.41 19.69,23.41 v1(19.97,23.69)
  BOTTOM w0.089: v1(12.98,23) 12.98,22.76 13.03,22.71 J2.27
SDMMC1_D1: length 17.9
  TOP w0.089: U3.D17 v2(16.88,15.96)
  GND02 w0.089: v1(19.51,23.79) 19.51,23.55 19.71,23.34 19.71,22.39 18.78,21.45 18.78,20.35 17.96,19.54 17.96,16.87 17.24,16.14 17.07,16.14 v2(16.88,15.96)
  LAYER_3 w0.089: v1(19.51,23.79) 19.24,24.07 13.93,24.07 13.52,23.66 v1(13.16,23.66)
  BOTTOM w0.089: J2.29 13.43,23.39 v1(13.16,23.66)
SDMMC1_D2: length 17.8
  TOP w0.089: U3.D15 v2(15.89,15.95)
  GND02 w0.089: v2(15.89,15.95) 15.44,16.4 15.44,18.7 15.68,18.94 15.68,20.69 15.37,21 14.71,21 14.63,21.07 14.63,21.3 14.74,21.4 15.09,21.4 15.17,21.48 15.17,21.76 15.07,21.87 13.62,21.87 13.56,21.93 13.56,22.25 13.62,22.32 13.82,22.32 13.9,22.39 13.9,22.6 13.81,22.68 13.66,22.68 13.57,22.77 13.57,22.95 13.66,23.04 13.81,23.04 13.9,23.13 13.9,23.24 13.99,23.33 14.14,23.33 14.23,23.42 14.23,23.6 14.14,23.69 13.94,23.69 13.85,23.78 13.85,24.01 13.94,24.1 14.7,24.1 14.84,23.96 14.84,23.23 v1(15.07,23)
  BOTTOM w0.089: v1(15.07,23) 14.89,23.18 14.89,23.31 14.66,23.54 13.97,23.54 13.83,23.39 J2.31
SDMMC1_D3: length 17.8
  TOP w0.089: U3.D16 v2(16.38,15.95)
  GND02 w0.089: v2(16.38,15.95) 16.79,16.36 16.79,16.63 16.97,16.81 17.23,16.81 17.76,17.33 17.76,19.38 17.68,19.45 v1(17.68,19.7)
  LAYER_3 w0.089: v1(14.33,22.27) 14.76,22.27 15.12,21.91 15.72,21.91 15.81,21.82 15.81,21.31 15.9,21.23 16.08,21.23 16.17,21.31 16.17,21.82 16.26,21.91 16.44,21.91 16.52,21.82 16.52,21.31 16.61,21.23 16.79,21.23 16.88,21.31 16.88,21.82 16.97,21.91 19.02,21.91 19.11,21.82 19.11,21.29 19.02,21.2 18.86,21.2 18.77,21.11 18.77,20.81 18.68,20.72 18.5,20.72 18.41,20.81 18.41,21.11 18.32,21.2 17.66,21.2 17.53,21.07 17.53,20.61 17.42,20.5 17.01,20.5 16.92,20.41 16.92,20.23 17.01,20.14 17.42,20.14 17.51,20.05 17.51,19.88 v1(17.68,19.7)
  BOTTOM w0.089: J2.33 14.23,22.17 v1(14.33,22.27)
SDMMC3_CLK: length 24.5
  TOP w0.089: v1(12.19,25.04) 12.19,24.62 12.07,24.51 11.29,24.51 11.21,24.42 11.21,24.22 11.29,24.13 11.78,24.13 11.87,24.04 11.87,22.75 11.5,22.39 11.5,22.04 12.09,21.46 12.09,18.41 12.13,18.37 12.13,17.2 U3.B7
  LAYER_3 w0.089: v1(12.19,25.04) 12.53,24.7 13.74,24.7 13.83,24.79 13.83,25 13.92,25.09 14.09,25.09 14.18,25 14.18,24.79 14.27,24.7 14.45,24.7 14.54,24.79 14.54,25 14.63,25.09 14.81,25.09 14.89,25 14.89,24.79 14.98,24.7 17.73,24.7 17.82,24.79 17.82,25.05 17.91,25.14 18.08,25.14 18.17,25.05 18.17,24.79 18.26,24.7 18.44,24.7 18.53,24.79 18.53,25.05 18.62,25.14 18.8,25.14 18.88,25.05 18.88,24.79 18.97,24.7 19.45,24.7 20.1,25.34 20.63,25.34 20.73,25.44 20.73,26.03 20.82,26.11 21.1,26.11 21.19,26.03 21.19,25.03 21.25,24.97 v1(21.5,24.97)
  BOTTOM w0.089: v1(21.5,24.97) 21.43,24.9 J2.70
SDMMC3_CMD: length 24.6
  TOP w0.089: U3.A5 10.88,18.54 10.95,18.61 v1(10.95,18.86)
  LAYER_3 w0.089: v1(10.34,25.34) 10.54,25.34 11.61,24.27 21.52,24.27 21.87,24.63 21.87,25.86 v1(21.35,26.39)
  LAYER_5 w0.089: v1(10.95,18.86) 10.95,19.32 10.91,19.37 10.91,21.14 10.55,21.5 10.55,23.58 10.54,23.59 10.54,23.6 10.1,24.04 10.1,25.09 v1(10.34,25.34)
  BOTTOM w0.089: J2.68 21.03,26.07 v1(21.35,26.39)
SDMMC3_D0: length 24.5
  TOP w0.089: v1(12.28,15.11) 12.28,15.67 12.38,15.77 U3.D8
  LAYER_3 w0.089: v1(14.43,26.6) 15.13,27.3 15.94,27.3 16.03,27.21 16.03,26.8 16.11,26.71 16.29,26.71 16.38,26.8 16.38,27.21 16.47,27.3 16.92,27.3 17.81,26.41 19.05,26.41 19.18,26.54 v1(19.43,26.54)
  LAYER_5 w0.089: v1(12.28,15.11) 12.28,21.21 12.32,21.25 12.32,21.25 13.02,21.95 13.02,22.37 12.67,22.72 12.67,24.04 12.76,24.13 13.1,24.13 13.19,24.22 13.19,24.39 13.1,24.48 12.76,24.48 12.67,24.57 12.67,26.19 12.81,26.33 13.22,26.33 13.31,26.24 13.31,26.06 13.4,25.97 13.58,25.97 13.67,26.06 13.67,26.24 13.76,26.33 14.16,26.33 v1(14.43,26.6)
  BOTTOM w0.089: v1(19.43,26.54) J2.60
